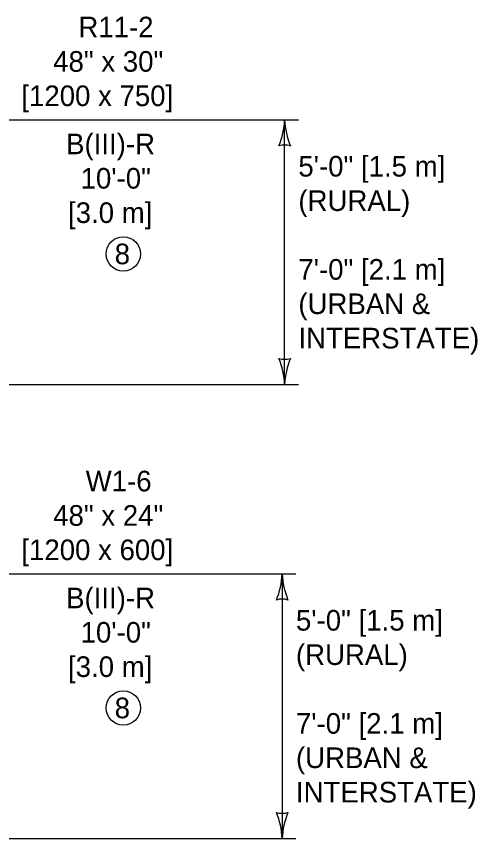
# Model space of a CAD drawing. Extents: x 49991.4 to 50021, y 49987.6 to 50011.4.
# Drawn here: x 50005.101 to 50006.442, y 49993.525 to 49995.917 of the extents above; entities that cross this region are included whole.
import ezdxf

# ---------------------------------------------------------------- set-up
doc = ezdxf.new("R2010")
doc.units = 0
doc.layers.add('Level 2', color=7, linetype='Continuous')
doc.layers.add('Level 3', color=7, linetype='Continuous')

msp = doc.modelspace()

# ---------------------------------------------------------------- linework, layer by layer
at = {"layer": 'Level 2'}
for centre in [(50005.4119, 49995.2257), (50005.4119, 49993.9049)]:
    msp.add_circle(centre, 0.05, dxfattribs=at)
at = {"layer": 'Level 3'}
for p, q in [((50004.7611, 49995.6157), (50005.9211, 49995.6157)), ((50005.8811, 49994.8457), (50005.8811, 49995.6157)), ((50004.7811, 49994.8457), (50005.9211, 49994.8457)), ((50004.7611, 49994.2949), (50005.914, 49994.2949)), ((50005.874, 49994.2949), (50005.874, 49993.5249)), ((50004.7811, 49993.5249), (50005.914, 49993.5249))]:
    msp.add_line(p, q, dxfattribs=at)
for centre, radius, start, end in [((50005.659, 49995.6249), 0.2223, 337.456, 357.6395), ((50006.1138, 49995.6272), 0.233, 182.8273, 202.0772), ((50005.8811, 49995.4875), 0.0548, 72.1388, 107.8612), ((50005.8811, 49994.9739), 0.0548, 252.1388, 287.8612), ((50005.6484, 49994.8342), 0.233, 2.8273, 22.0772), ((50006.1033, 49994.8365), 0.2223, 157.456, 177.6395), ((50005.6519, 49994.3041), 0.2223, 337.456, 357.6395), ((50006.1067, 49994.3064), 0.233, 182.8273, 202.0772), ((50005.874, 49994.1667), 0.0548, 72.1388, 107.8612), ((50005.874, 49993.6531), 0.0548, 252.1388, 287.8612), ((50005.6413, 49993.5134), 0.233, 2.8273, 22.0772), ((50006.0962, 49993.5157), 0.2223, 157.456, 177.6395)]:
    msp.add_arc(centre, radius, start, end, dxfattribs=at)

# ---------------------------------------------------------------- texts
at = {"layer": 'Level 2'}
for s, p in [('R11-2', (50005.2813, 49995.8557)), ('48" x 30"', (50005.2081, 49995.7557)), ('[1200 x 750]', (50005.1155, 49995.6557)), ('B(III)-R', (50005.2456, 49995.5157)), ('5\'-0" [1.5 m]', (50005.9211, 49995.4507)), (' 10\'-0"', (50005.2655, 49995.4157)), ('(RURAL)', (50005.9211, 49995.3507)), ('[3.0 m]', (50005.2512, 49995.3157)), ('8', (50005.3869, 49995.1957)), ('7\'-0" [2.1 m]', (50005.9211, 49995.1507)), ('(URBAN &', (50005.9211, 49995.0507)), ('INTERSTATE)', (50005.9211, 49994.9507)), ('W1-6', (50005.3025, 49994.5349)), ('48" x 24"', (50005.2081, 49994.4349)), ('[1200 x 600]', (50005.1155, 49994.3349)), ('B(III)-R', (50005.2456, 49994.1949)), ('5\'-0" [1.5 m]', (50005.914, 49994.1299)), (' 10\'-0"', (50005.2655, 49994.0949)), ('(RURAL)', (50005.914, 49994.0299)), ('[3.0 m]', (50005.2512, 49993.9949)), ('8', (50005.3869, 49993.8749)), ('7\'-0" [2.1 m]', (50005.914, 49993.8299)), ('(URBAN &', (50005.914, 49993.7299)), ('INTERSTATE)', (50005.914, 49993.6299))]:
    msp.add_text(s, height=0.06, dxfattribs=at).set_placement(p)

doc.saveas('drawing.dxf')
